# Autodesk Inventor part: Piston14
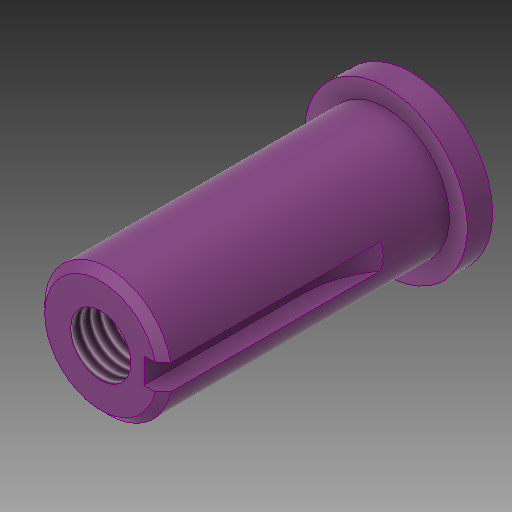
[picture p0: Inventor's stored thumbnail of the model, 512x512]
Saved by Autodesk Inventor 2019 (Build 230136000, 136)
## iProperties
Created: 2019-02
Part Number: Piston14
Material: Générique
Document SubType Name: Modeling
Designer: si-nd67
Density: 1 g/cm^3
Appearance: Lisse - Violet
Mass: 21.5536 g
Surface Area: 91.2049 cm^2
Volume: 21.5536 cm^3
Author: si-nd67
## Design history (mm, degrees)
sketch "Esquisse1"
  geometry: L1 (0, 27.984)-(12.5, 27.984); L2 (12.5, 27.984)-(12.5, -28.016); L3 (12.5, -28.016)-(16, -28.016); L4 (16, -28.016)-(16, -33.016); L5 (16, -33.016)-(0, -33.016); L6 (0, -33.016)-(0, 27.984); 1 further point
  constraints: 12 end point, 5 perpendicular, 1 horizontal
  dimensions: "d0" = 25 diameter of L2 L6; "d1" = 5 distance of L3.end L4.end; "d2" = 32 diameter of L4 L6; "d3" = 56 distance of L1.end L2.end
revolve "Révolution1" sketch "Esquisse1" stored, may be unused: angle "d4" = 90 deg
sketch "Esquisse2"
  geometry: C1 r 7.5 at (0, 0); 1 further point
  constraints: 1 centre point, 1 coincident
  dimensions: "d5" = 15 diameter of C1
extrude "Extrusion1" cut sketch "Esquisse2" distance "d6" = 36; taper "d7" = 0 deg
sketch "Esquisse3"
  geometry: 2 further points
  constraints: 1 coincident
hole "Perçage1" sketch "Esquisse3" at (0, 0) diameter "d8" = 11.835; stored, may be unused: countersink angle "d12" = 90 deg, drill point angle "d14" = 0 deg; dims "d9" = 25, "d10" = 4, "d11" = 2, "d13" = 25
sketch "Esquisse5"
  geometry: L1 (-8.5, 52.101)-(-8.5, -3.016); L2 (-12.5, 27.984)-(12.5, 27.984) reference; L3 (-48.5, -3.016)-(-48.5, 52.101); L4 (-8.5, 52.101)-(-48.5, 52.101); A1 r 20 centre (-28.5, -3.016) between (-48.5, -3.016) and (-8.5, -3.016); 1 further point
  constraints: 6 end point, 2 point on circle, 2 tangent, 2 vertical, 1 centre point, 1 horizontal
  dimensions: "d15" = 40 diameter of A1; "d16" = 31 distance from line of A1.centre L2; "d17" = 8.5 distance from line of L1 point (0, 0); "d18" = 55.11758 distance of L3.start L3.end
extrude "Extrusion2" cut sketch "Esquisse5" stored distance "d19" = 5; taper "d20" = 0 deg
chamfer "Chanfrein1" distance "d21" = 1.5; stored, may be unused: second distance "d22" = 2, angle "d23" = 45 deg
node "Solide1"
